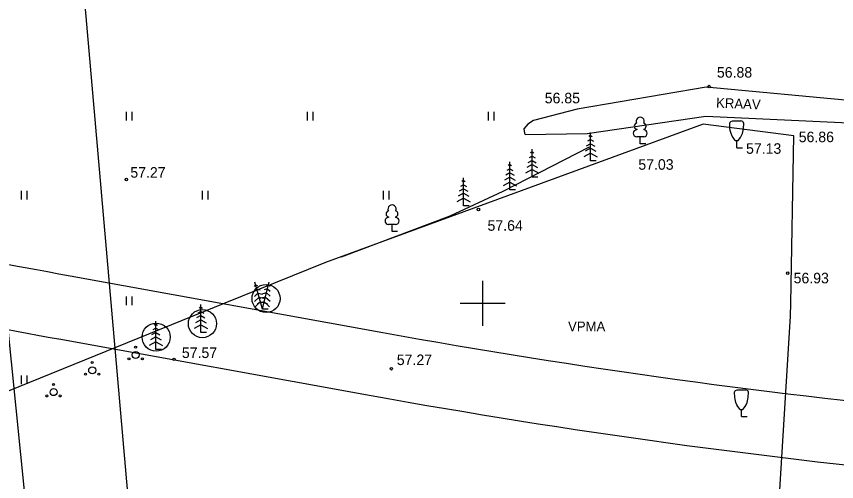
# Model space of a CAD drawing. Extents: x 9156 to 9809, y 2728 to 4000.
# Drawn here: x 9316.8 to 9375.2, y 3737.3 to 3770.4 of the extents above; entities that cross this region are included whole.
import ezdxf

# ---------------------------------------------------------------- set-up
doc = ezdxf.new("R2010")
doc.units = 0
for name, color, linetype in [('Level 1', 7, 'Continuous'), ('Level 17', 7, 'Continuous'), ('Level 18', 7, 'Continuous'), ('Level 21', 7, 'Continuous'), ('Level 54', 7, 'Continuous'), ('Level 56', 7, 'Continuous'), ('Level 6', 7, 'Continuous')]:
    doc.layers.add(name, color=color, linetype=linetype)

msp = doc.modelspace()

# ---------------------------------------------------------------- linework, layer by layer
at = {"layer": 'Level 1'}
msp.add_line((9317.65, 3734.12), (9308.72, 3821.62), dxfattribs=at)
msp.add_line((9317.65, 3734.12), (9308.72, 3821.62), dxfattribs=at)
at = {"layer": 'Level 17'}
msp.add_line((9320.627, 3751.957), (9342.885, 3747.92), dxfattribs=at)
for centre, start, end in [((9408.833, 4238.272), 256.69765, 259.71972), ((9431.091, 4234.235), 259.71972, 264.63885)]:
    msp.add_arc(centre, 494.25, start, end, dxfattribs=at)
at = {"layer": 'Level 18'}
msp.add_line((9319.813, 3747.465), (9342.071, 3743.428), dxfattribs=at)
for centre, radius, start, end in [((9408.833, 4238.272), 498.82, 256.91824, 259.71972), ((9431.091, 4234.235), 498.804, 259.71972, 264.63885)]:
    msp.add_arc(centre, radius, start, end, dxfattribs=at)
at = {"layer": 'Level 21'}
for centre in [(9334.578, 3750.339), (9330.047, 3748.553), (9326.753, 3747.592)]:
    msp.add_circle(centre, 1, dxfattribs=at)
at = {"layer": 'Level 54'}
for p, q in [((9365.921, 3765.387), (9356.718, 3763.803)), ((9380.085, 3764.042), (9365.921, 3765.387)), ((9324.625, 3763.634), (9324.625, 3763.013)), ((9325.03, 3763.622), (9325.03, 3763.013)), ((9337.506, 3763.634), (9337.506, 3763.013)), ((9337.912, 3763.622), (9337.912, 3763.013)), ((9350.388, 3763.634), (9350.388, 3763.013)), ((9350.793, 3763.622), (9350.793, 3763.013)), ((9356.718, 3763.803), (9353.624, 3763.01)), ((9353.624, 3763.01), (9353.211, 3762.734)), ((9357.43, 3762.077), (9365.887, 3763.318)), ((9365.887, 3763.318), (9378.813, 3762.698)), ((9365.69, 3762.747), (9338.799, 3752.897)), ((9353.211, 3762.734), (9352.936, 3762.424)), ((9352.936, 3762.424), (9352.97, 3762.114)), ((9372.153, 3761.919), (9365.69, 3762.747)), ((9367.788, 3762.973), (9368.388, 3762.973)), ((9352.97, 3762.114), (9353.029, 3762.008)), ((9353.029, 3762.008), (9357.43, 3762.077)), ((9357.677, 3761.943), (9357.551, 3761.873)), ((9357.677, 3760.143), (9357.677, 3762.143)), ((9357.677, 3761.943), (9357.803, 3761.873)), ((9360.968, 3762.381), (9360.968, 3762.349)), ((9361.468, 3761.849), (9360.968, 3761.849)), ((9361.218, 3761.349), (9361.218, 3761.849)), ((9361.468, 3762.381), (9361.468, 3762.349)), ((9371.929, 3750), (9372.153, 3761.919)), ((9357.677, 3761.343), (9357.379, 3761.177)), ((9357.677, 3761.643), (9357.465, 3761.525)), ((9357.677, 3761.643), (9357.889, 3761.525)), ((9357.677, 3761.343), (9357.975, 3761.177)), ((9361.618, 3761.349), (9361.218, 3761.349)), ((9367.988, 3761.573), (9368.188, 3761.573)), ((9368.088, 3761.073), (9368.088, 3761.573)), ((9353.517, 3760.77), (9353.391, 3760.7)), ((9353.517, 3758.97), (9353.517, 3760.97)), ((9353.517, 3760.77), (9353.643, 3760.7)), ((9357.677, 3760.693), (9357.202, 3760.429)), ((9357.677, 3761.043), (9357.293, 3760.829)), ((9357.677, 3761.043), (9358.061, 3760.829)), ((9357.677, 3760.693), (9358.152, 3760.429)), ((9368.088, 3761.073), (9368.488, 3761.073)), ((9351.936, 3758.074), (9351.936, 3760.074)), ((9353.517, 3760.17), (9353.219, 3760.005)), ((9353.517, 3760.47), (9353.305, 3760.353)), ((9353.517, 3760.47), (9353.729, 3760.353)), ((9353.517, 3760.17), (9353.815, 3760.005)), ((9358.077, 3760.143), (9357.677, 3760.143)), ((9351.936, 3759.574), (9351.724, 3759.456)), ((9351.936, 3759.874), (9351.81, 3759.804)), ((9351.936, 3759.874), (9352.062, 3759.804)), ((9351.936, 3759.574), (9352.148, 3759.456)), ((9353.517, 3759.52), (9353.042, 3759.256)), ((9353.517, 3759.87), (9353.133, 3759.657)), ((9353.517, 3759.87), (9353.901, 3759.657)), ((9353.517, 3759.52), (9353.992, 3759.256)), ((9348.635, 3756.936), (9348.635, 3758.936)), ((9351.936, 3758.974), (9351.552, 3758.761)), ((9351.936, 3759.274), (9351.638, 3759.108)), ((9351.936, 3759.274), (9352.234, 3759.108)), ((9351.936, 3758.974), (9352.32, 3758.761)), ((9353.917, 3758.97), (9353.517, 3758.97)), ((9348.635, 3758.436), (9348.423, 3758.318)), ((9348.635, 3758.736), (9348.509, 3758.666)), ((9348.635, 3758.736), (9348.761, 3758.666)), ((9348.635, 3758.436), (9348.847, 3758.318)), ((9351.936, 3758.624), (9351.46, 3758.36)), ((9351.936, 3758.624), (9352.411, 3758.36)), ((9317.149, 3758.013), (9317.149, 3757.393)), ((9317.554, 3758.002), (9317.554, 3757.393)), ((9330.03, 3758.013), (9330.03, 3757.393)), ((9330.436, 3758.002), (9330.436, 3757.393)), ((9342.912, 3758.013), (9342.912, 3757.393)), ((9343.317, 3758.002), (9343.317, 3757.393)), ((9348.635, 3757.836), (9348.251, 3757.623)), ((9348.635, 3758.136), (9348.337, 3757.971)), ((9348.635, 3758.136), (9348.933, 3757.971)), ((9348.635, 3757.836), (9349.019, 3757.623)), ((9352.336, 3758.074), (9351.936, 3758.074)), ((9348.635, 3757.486), (9348.16, 3757.222)), ((9348.635, 3757.486), (9349.111, 3757.222)), ((9349.035, 3756.936), (9348.635, 3756.936)), ((9343.297, 3756.141), (9343.297, 3756.109)), ((9343.797, 3756.141), (9343.797, 3756.109)), ((9343.797, 3755.609), (9343.297, 3755.609)), ((9343.547, 3755.109), (9343.547, 3755.609)), ((9343.947, 3755.109), (9343.547, 3755.109)), ((9338.799, 3752.897), (9331.65, 3750)), ((9334.199, 3750), (9333.775, 3751.494)), ((9334.428, 3750), (9334.802, 3751.511)), ((9334.754, 3751.317), (9334.615, 3751.279)), ((9334.754, 3751.317), (9334.859, 3751.219)), ((9350, 3751.593), (9350, 3750)), ((9350, 3751.593), (9350, 3750)), ((9333.83, 3751.301), (9333.728, 3751.2)), ((9333.912, 3751.013), (9333.74, 3750.842)), ((9333.83, 3751.301), (9333.97, 3751.268)), ((9333.912, 3751.013), (9334.148, 3750.957)), ((9334.61, 3750.734), (9334.281, 3750.645)), ((9334.682, 3751.026), (9334.448, 3750.962)), ((9334.61, 3750.734), (9334.859, 3750.502)), ((9334.682, 3751.026), (9334.859, 3750.86)), ((9350, 3751.25), (9350, 3748.75)), ((9324.625, 3750.482), (9324.625, 3750)), ((9325.03, 3750.471), (9325.03, 3750)), ((9333.994, 3750.724), (9333.752, 3750.484)), ((9334.076, 3750.436), (9333.764, 3750.126)), ((9333.994, 3750.724), (9334.326, 3750.646)), ((9334.076, 3750.436), (9334.503, 3750.335)), ((9334.537, 3750.443), (9334.114, 3750.329)), ((9334.537, 3750.443), (9334.859, 3750.144)), ((9331.65, 3750), (9311.976, 3742.025)), ((9324.625, 3750), (9324.625, 3749.862)), ((9325.03, 3750), (9325.03, 3749.862)), ((9329.933, 3749.724), (9329.807, 3749.654)), ((9329.933, 3747.924), (9329.933, 3749.924)), ((9329.933, 3749.724), (9330.059, 3749.654)), ((9334.072, 3750), (9333.806, 3749.736)), ((9334.071, 3750), (9333.956, 3749.969)), ((9334.453, 3750.104), (9334.071, 3750)), ((9334.171, 3750.099), (9334.072, 3750)), ((9334.171, 3750.099), (9334.592, 3750)), ((9334.321, 3749.57), (9334.199, 3750)), ((9334.321, 3749.57), (9334.428, 3750)), ((9334.721, 3749.57), (9334.321, 3749.57)), ((9334.453, 3750.104), (9334.564, 3750)), ((9334.564, 3750), (9334.83, 3749.753)), ((9334.592, 3750), (9334.672, 3749.981)), ((9348.407, 3750), (9351.593, 3750)), ((9348.407, 3750), (9351.593, 3750)), ((9348.407, 3750), (9351.593, 3750)), ((9348.407, 3750), (9351.593, 3750)), ((9348.75, 3750), (9351.25, 3750)), ((9350, 3750), (9350, 3748.407)), ((9350, 3750), (9350, 3748.407)), ((9371.912, 3749.093), (9371.929, 3750)), ((9329.933, 3749.124), (9329.635, 3748.959)), ((9329.933, 3749.424), (9329.721, 3749.307)), ((9329.933, 3749.424), (9330.145, 3749.307)), ((9329.933, 3749.124), (9330.231, 3748.959)), ((9371.063, 3735.367), (9371.912, 3749.093)), ((9326.725, 3748.518), (9326.599, 3748.448)), ((9326.725, 3746.718), (9326.725, 3748.718)), ((9326.725, 3748.518), (9326.851, 3748.448)), ((9329.933, 3748.474), (9329.458, 3748.21)), ((9329.933, 3748.824), (9329.549, 3748.611)), ((9329.933, 3748.824), (9330.317, 3748.611)), ((9329.933, 3748.474), (9330.409, 3748.21)), ((9326.725, 3747.918), (9326.427, 3747.752)), ((9326.725, 3748.218), (9326.513, 3748.1)), ((9326.725, 3748.218), (9326.937, 3748.1)), ((9326.725, 3747.918), (9327.023, 3747.752)), ((9330.333, 3747.924), (9329.933, 3747.924)), ((9326.725, 3747.268), (9326.25, 3747.004)), ((9326.725, 3747.618), (9326.341, 3747.405)), ((9326.725, 3747.618), (9327.109, 3747.405)), ((9326.725, 3747.268), (9327.2, 3747.004)), ((9327.125, 3746.718), (9326.725, 3746.718)), ((9317.149, 3744.862), (9317.149, 3744.242)), ((9317.554, 3744.851), (9317.554, 3744.286)), ((9368.129, 3743.842), (9368.729, 3743.842)), ((9368.329, 3742.442), (9368.529, 3742.442)), ((9368.429, 3741.942), (9368.429, 3742.442)), ((9368.429, 3741.942), (9368.829, 3741.942))]:
    msp.add_line(p, q, dxfattribs=at)
for points in [[(9367.988, 3761.573), (9367.83, 3761.786), (9367.765, 3761.898), (9367.688, 3762.073), (9367.627, 3762.299), (9367.603, 3762.455), (9367.588, 3762.773), (9367.59, 3762.815), (9367.62, 3762.886), (9367.66, 3762.924), (9367.788, 3762.973)], [(9368.188, 3761.573), (9368.346, 3761.786), (9368.411, 3761.898), (9368.488, 3762.073), (9368.549, 3762.299), (9368.573, 3762.455), (9368.588, 3762.773), (9368.586, 3762.815), (9368.556, 3762.886), (9368.516, 3762.924), (9368.388, 3762.973)], [(9339.94, 3753.316), (9347.675, 3756.212), (9351.457, 3757.971), (9357.611, 3761.143)], [(9368.329, 3742.442), (9368.171, 3742.655), (9368.106, 3742.767), (9368.029, 3742.942), (9367.968, 3743.167), (9367.944, 3743.323), (9367.929, 3743.642), (9367.931, 3743.683), (9367.961, 3743.755), (9368.001, 3743.792), (9368.129, 3743.842)], [(9368.529, 3742.442), (9368.688, 3742.655), (9368.752, 3742.767), (9368.829, 3742.942), (9368.891, 3743.167), (9368.914, 3743.323), (9368.929, 3743.642), (9368.927, 3743.683), (9368.898, 3743.755), (9368.857, 3743.792), (9368.729, 3743.842)]]:
    msp.add_lwpolyline(points, dxfattribs=at)
for centre, radius in [((9366.121, 3765.418), 0.0909), ((9324.631, 3758.812), 0.0909), ((9349.696, 3756.678), 0.0909), ((9371.718, 3752.144), 0.0909), ((9325.294, 3746.871), 0.0707), ((9324.818, 3746.046), 0.0707), ((9325.294, 3746.321), 0.25), ((9325.771, 3746.046), 0.0707), ((9328.026, 3746.014), 0.0909), ((9322.201, 3745.229), 0.25), ((9322.201, 3745.779), 0.0707), ((9321.724, 3744.954), 0.0707), ((9322.677, 3744.954), 0.0707), ((9343.499, 3745.343), 0.0909), ((9319.451, 3743.678), 0.25), ((9319.451, 3744.228), 0.0707), ((9318.975, 3743.403), 0.0707), ((9319.927, 3743.403), 0.0707)]:
    msp.add_circle(centre, radius, dxfattribs=at)
for centre, radius, start, end in [((9361.218, 3762.949), 0.292, 332.5799, 207.4201), ((9361.018, 3762.599), 0.224, 105.2441, 257.07903), ((9361.418, 3762.599), 0.224, 282.92097, 74.7559), ((9360.968, 3762.099), 0.25, 90.00001, 270), ((9361.468, 3762.099), 0.25, 270, 89.99999), ((9343.347, 3756.359), 0.224, 105.2441, 257.07903), ((9343.547, 3756.709), 0.292, 332.5799, 207.4201), ((9343.747, 3756.359), 0.224, 282.92097, 74.7559), ((9343.297, 3755.859), 0.25, 90.00001, 270), ((9343.797, 3755.859), 0.25, 270, 89.99999)]:
    msp.add_arc(centre, radius, start, end, dxfattribs=at)
at = {"layer": 'Level 56'}
for p, q in [((9320.627, 3751.957), (9342.885, 3747.92)), ((9319.813, 3747.465), (9342.071, 3743.428))]:
    msp.add_line(p, q, dxfattribs=at)
for centre, radius, start, end in [((9408.833, 4238.272), 494.25, 256.69765, 259.71972), ((9408.833, 4238.272), 498.82, 256.91824, 259.71972), ((9431.091, 4234.235), 494.25, 259.71972, 264.63885), ((9431.091, 4234.235), 498.804, 259.71972, 264.63885)]:
    msp.add_arc(centre, radius, start, end, dxfattribs=at)
at = {"layer": 'Level 6'}
msp.add_line((9306.372, 3945.862), (9356.727, 3371.389), dxfattribs=at)

# ---------------------------------------------------------------- texts
at = {"layer": 'Level 54'}
for s, height, p in [('56.88', 0.75, (9366.678, 3766.058)), ('56.85', 0.75, (9354.42, 3764.229)), ('56.86', 0.75, (9372.502, 3761.463)), ('57.13', 0.75, (9368.752, 3760.636)), ('57.03', 0.75, (9361.083, 3759.501)), ('57.27', 0.75, (9324.915, 3758.936)), ('57.64', 0.75, (9350.347, 3755.158)), ('56.93', 0.75, (9372.138, 3751.42)), ('VPMA', 0.7, (9356.079, 3748.002)), ('57.57', 0.75, (9328.585, 3746.104)), ('57.27', 0.75, (9343.887, 3745.604))]:
    msp.add_text(s, height=height, dxfattribs=at).set_placement(p)
msp.add_text('KRAAV', height=0.7, rotation=357.50324, dxfattribs=at).set_placement((9366.607, 3763.926))

doc.saveas('drawing.dxf')
